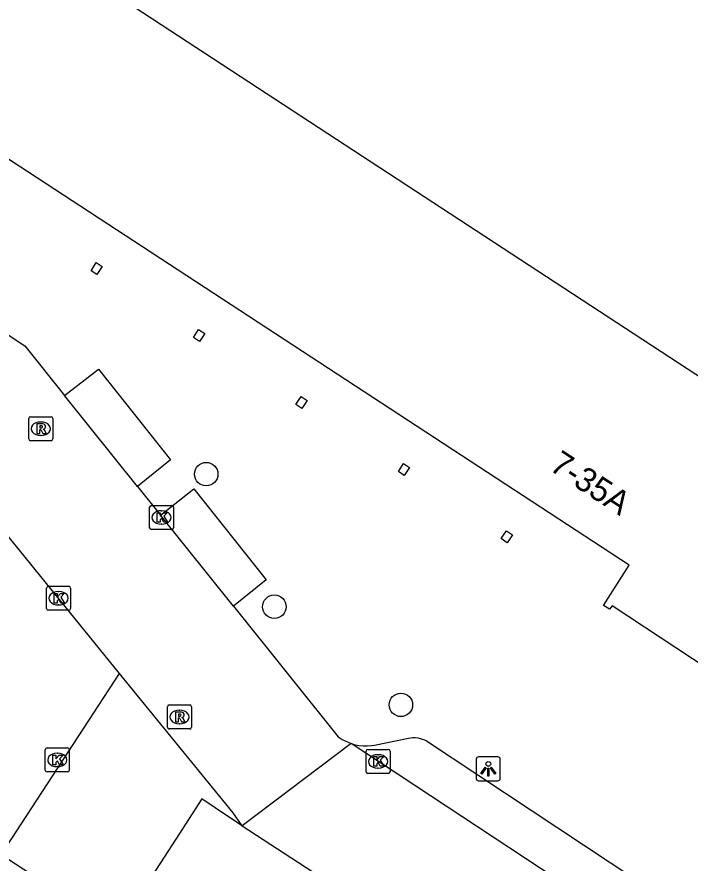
# Model space of a CAD drawing. Extents: x 159280 to 160375, y 384531 to 385872.
# Drawn here: x 159762.98 to 159791.01, y 385030.75 to 385066 of the extents above; entities that cross this region are included whole.
import ezdxf

# ---------------------------------------------------------------- set-up
doc = ezdxf.new("R2010")
doc.units = 0
for name, color, linetype in [('IMGEO_Boom', 7, 'Continuous'), ('IMGEO_Kolk', 7, 'Continuous'), ('IMGEO_Lichtpunt', 7, 'Continuous'), ('IMGEO_Pand', 7, 'Continuous'), ('IMGEO_Pand_nummerreeks', 7, 'Continuous'), ('IMGEO_Rijbaan_lokaal_open', 7, 'Continuous'), ('IMGEO_Rioolput', 7, 'Continuous'), ('IMGEO_Voetpad_open', 7, 'Continuous')]:
    doc.layers.add(name, color=color, linetype=linetype)

msp = doc.modelspace()

# ---------------------------------------------------------------- linework, layer by layer
at = {"layer": 'IMGEO_Boom'}
for centre in [(159770.864, 385046.949), (159773.702, 385041.427), (159778.971, 385037.338)]:
    msp.add_circle(centre, 0.489, dxfattribs=at)
at = {"layer": 'IMGEO_Kolk'}
for p, q in [((159768.506, 385044.718), (159768.506, 385045.57)), ((159768.581, 385045.644), (159769.433, 385045.644)), ((159769.507, 385045.57), (159769.507, 385044.718)), ((159768.994, 385045.424), (159769.019, 385045.424)), ((159769.017, 385044.864), (159768.992, 385044.864)), ((159769.433, 385044.644), (159768.581, 385044.644)), ((159764.218, 385041.352), (159764.218, 385042.204)), ((159764.293, 385042.278), (159765.145, 385042.278)), ((159764.706, 385042.058), (159764.731, 385042.058)), ((159765.219, 385042.204), (159765.219, 385041.352)), ((159765.145, 385041.278), (159764.293, 385041.278)), ((159764.729, 385041.498), (159764.704, 385041.498)), ((159764.164, 385034.618), (159764.164, 385035.47)), ((159764.239, 385035.544), (159765.091, 385035.544)), ((159764.652, 385035.324), (159764.677, 385035.324)), ((159765.165, 385035.47), (159765.165, 385034.618)), ((159777.518, 385034.554), (159777.518, 385035.406)), ((159777.593, 385035.48), (159778.445, 385035.48)), ((159778.006, 385035.26), (159778.031, 385035.26)), ((159778.519, 385035.406), (159778.519, 385034.554)), ((159765.091, 385034.544), (159764.239, 385034.544)), ((159764.675, 385034.764), (159764.65, 385034.764)), ((159778.029, 385034.7), (159778.004, 385034.7)), ((159778.445, 385034.48), (159777.593, 385034.48))]:
    msp.add_line(p, q, dxfattribs=at)
for points in [[(159768.506, 385044.718), (159768.506, 385045.57)], [(159768.581, 385045.644), (159769.433, 385045.644)], [(159769.507, 385045.57), (159769.507, 385044.718)], [(159768.827, 385045.344), (159768.95, 385045.344), (159768.95, 385045.193), (159769.08, 385045.344), (159769.244, 385045.344), (159769.098, 385045.193), (159769.251, 385044.944), (159769.099, 385044.944), (159769.014, 385045.108), (159768.95, 385045.041), (159768.95, 385044.944), (159768.827, 385044.944), (159768.827, 385045.344)], [(159769.433, 385044.644), (159768.581, 385044.644)], [(159764.218, 385041.352), (159764.218, 385042.204)], [(159764.293, 385042.278), (159765.145, 385042.278)], [(159764.539, 385041.978), (159764.662, 385041.978), (159764.662, 385041.827), (159764.792, 385041.978), (159764.956, 385041.978), (159764.81, 385041.827), (159764.963, 385041.578), (159764.811, 385041.578), (159764.726, 385041.742), (159764.662, 385041.675), (159764.662, 385041.578), (159764.539, 385041.578), (159764.539, 385041.978)], [(159765.219, 385042.204), (159765.219, 385041.352)], [(159765.145, 385041.278), (159764.293, 385041.278)], [(159764.164, 385034.618), (159764.164, 385035.47)], [(159764.239, 385035.544), (159765.091, 385035.544)], [(159764.485, 385035.244), (159764.608, 385035.244), (159764.608, 385035.093), (159764.738, 385035.244), (159764.902, 385035.244), (159764.756, 385035.093), (159764.909, 385034.844), (159764.757, 385034.844), (159764.672, 385035.008), (159764.608, 385034.941), (159764.608, 385034.844), (159764.485, 385034.844), (159764.485, 385035.244)], [(159765.165, 385035.47), (159765.165, 385034.618)], [(159777.518, 385034.554), (159777.518, 385035.406)], [(159777.593, 385035.48), (159778.445, 385035.48)], [(159778.519, 385035.406), (159778.519, 385034.554)], [(159777.839, 385035.18), (159777.962, 385035.18), (159777.962, 385035.029), (159778.092, 385035.18), (159778.256, 385035.18), (159778.11, 385035.029), (159778.263, 385034.78), (159778.111, 385034.78), (159778.026, 385034.944), (159777.962, 385034.877), (159777.962, 385034.78), (159777.839, 385034.78), (159777.839, 385035.18)], [(159765.091, 385034.544), (159764.239, 385034.544)], [(159778.445, 385034.48), (159777.593, 385034.48)]]:
    msp.add_lwpolyline(points, dxfattribs=at)
for centre, start, end in [((159768.583, 385045.568), 91.552, 178.448), ((159768.583, 385045.568), 91.552, 178.448), ((159769.431, 385045.568), 1.552, 88.448), ((159769.431, 385045.568), 1.552, 88.448), ((159768.583, 385044.72), 181.552, 268.448), ((159768.583, 385044.72), 181.552, 268.448), ((159769.431, 385044.72), 271.552, 358.448), ((159769.431, 385044.72), 271.552, 358.448), ((159764.295, 385042.202), 91.552, 178.448), ((159764.295, 385042.202), 91.552, 178.448), ((159765.143, 385042.202), 1.552, 88.448), ((159765.143, 385042.202), 1.552, 88.448), ((159764.295, 385041.354), 181.552, 268.448), ((159764.295, 385041.354), 181.552, 268.448), ((159765.143, 385041.354), 271.552, 358.448), ((159765.143, 385041.354), 271.552, 358.448), ((159764.241, 385035.468), 91.552, 178.448), ((159764.241, 385035.468), 91.552, 178.448), ((159765.089, 385035.468), 1.552, 88.448), ((159765.089, 385035.468), 1.552, 88.448), ((159777.595, 385035.404), 91.552, 178.448), ((159777.595, 385035.404), 91.552, 178.448), ((159778.443, 385035.404), 1.552, 88.448), ((159778.443, 385035.404), 1.552, 88.448), ((159764.241, 385034.62), 181.552, 268.448), ((159764.241, 385034.62), 181.552, 268.448), ((159765.089, 385034.62), 271.552, 358.448), ((159765.089, 385034.62), 271.552, 358.448), ((159777.595, 385034.556), 181.552, 268.448), ((159777.595, 385034.556), 181.552, 268.448), ((159778.443, 385034.556), 271.552, 358.448), ((159778.443, 385034.556), 271.552, 358.448)]:
    msp.add_arc(centre, 0.0765, start, end, dxfattribs=at)
for centre, major_axis, ratio, start_param, end_param in [((159768.993, 385045.144), (-0.387, 0.002), 0.722429, 4.712389, 7.853982), ((159769.018, 385045.144), (-0.39, 0.002), 0.717154, 1.570796, 4.712389), ((159764.705, 385041.778), (-0.387, 0.002), 0.722429, 4.712389, 7.853982), ((159764.73, 385041.778), (-0.39, 0.002), 0.717154, 1.570796, 4.712389), ((159764.651, 385035.044), (-0.387, 0.002), 0.722429, 4.712389, 7.853982), ((159764.676, 385035.044), (-0.39, 0.002), 0.717154, 1.570796, 4.712389), ((159778.005, 385034.98), (-0.387, 0.002), 0.722429, 4.712389, 7.853982), ((159778.03, 385034.98), (-0.39, 0.002), 0.717154, 1.570796, 4.712389)]:
    msp.add_ellipse(centre, major_axis=major_axis, ratio=ratio, start_param=start_param, end_param=end_param, dxfattribs=at)
at = {"layer": 'IMGEO_Lichtpunt'}
for p, q in [((159782.11, 385035.078), (159782.11, 385034.271)), ((159782.11, 385035.078), (159782.11, 385034.271)), ((159783.012, 385035.173), (159782.204, 385035.173)), ((159783.012, 385035.173), (159782.204, 385035.173)), ((159783.106, 385034.271), (159783.106, 385035.078)), ((159783.106, 385034.271), (159783.106, 385035.078)), ((159782.204, 385034.177), (159783.012, 385034.177)), ((159782.204, 385034.177), (159783.012, 385034.177))]:
    msp.add_line(p, q, dxfattribs=at)
for points in [[(159782.484, 385034.742), (159782.523, 385034.714), (159782.335, 385034.452), (159782.297, 385034.479), (159782.484, 385034.742)], [(159782.586, 385034.694), (159782.633, 385034.694), (159782.633, 385034.372), (159782.586, 385034.372), (159782.586, 385034.694)], [(159782.696, 385034.714), (159782.734, 385034.741), (159782.921, 385034.479), (159782.882, 385034.451), (159782.696, 385034.714)]]:
    msp.add_lwpolyline(points, dxfattribs=at)
msp.add_circle((159782.609, 385034.876), 0.0994, dxfattribs=at)
for centre, start, end in [((159782.204, 385035.078), 90, 180), ((159782.204, 385035.078), 90, 180), ((159783.012, 385035.078), 0, 90), ((159783.012, 385035.078), 0, 90), ((159782.204, 385034.271), 180, 270), ((159782.204, 385034.271), 180, 270), ((159783.012, 385034.271), 270, 0), ((159783.012, 385034.271), 270, 360)]:
    msp.add_arc(centre, 0.0946, start, end, dxfattribs=at)
at = {"layer": 'IMGEO_Pand'}
for points in [[(159758.939, 385075.975), (159757.257, 385073.372), (159759.826, 385071.675), (159812.424, 385037.26), (159815.331, 385041.68), (159815.513, 385041.56)], [(159791.768, 385038.831), (159787.771, 385041.458), (159787.659, 385041.318), (159787.407, 385041.476), (159788.477, 385043.151), (159750.544, 385067.986), (159749.427, 385066.306), (159744.541, 385069.513)], [(159766.281, 385055.765), (159766.535, 385055.599), (159766.315, 385055.266), (159766.072, 385055.423), (159766.281, 385055.765)], [(159770.542, 385052.975), (159770.801, 385052.81), (159770.582, 385052.476), (159770.331, 385052.637), (159770.542, 385052.975)], [(159774.812, 385050.183), (159775.065, 385050.017), (159774.846, 385049.683), (159774.601, 385049.845), (159774.812, 385050.183)], [(159779.078, 385047.396), (159779.332, 385047.231), (159779.113, 385046.896), (159778.866, 385047.056), (159779.078, 385047.396)], [(159783.366, 385044.593), (159783.62, 385044.428), (159783.401, 385044.093), (159783.14, 385044.267), (159783.366, 385044.593)]]:
    msp.add_lwpolyline(points, dxfattribs=at)
at = {"layer": 'IMGEO_Rijbaan_lokaal_open'}
for points in [[(159762.407, 385052.895), (159763.312, 385052.296), (159764.967, 385050.229)], [(159768.003, 385046.438), (159764.967, 385050.229)], [(159768.003, 385046.438), (159768.959, 385045.245)], [(159771.997, 385041.451), (159768.959, 385045.245)], [(159767.259, 385038.65), (159762.49, 385044.521)], [(159771.997, 385041.451), (159776.359, 385036.004), (159776.519, 385035.899), (159776.906, 385035.721)], [(159762.324, 385031.093), (159767.259, 385038.65)], [(159772.362, 385032.302), (159771.983, 385032.834), (159767.259, 385038.65)], [(159776.906, 385035.721), (159772.362, 385032.302)], [(159803.235, 385018.337), (159776.906, 385035.721)], [(159772.362, 385032.302), (159780.636, 385026.908)]]:
    msp.add_lwpolyline(points, dxfattribs=at)
at = {"layer": 'IMGEO_Rioolput'}
for p, q in [((159763.552, 385049.342), (159764.404, 385049.342)), ((159763.477, 385048.416), (159763.477, 385049.268)), ((159763.965, 385049.122), (159763.99, 385049.122)), ((159764.478, 385049.268), (159764.478, 385048.416)), ((159764.404, 385048.342), (159763.552, 385048.342)), ((159763.988, 385048.562), (159763.963, 385048.562)), ((159769.249, 385036.406), (159769.249, 385037.258)), ((159769.324, 385037.332), (159770.176, 385037.332)), ((159769.737, 385037.112), (159769.762, 385037.112)), ((159770.25, 385037.258), (159770.25, 385036.406)), ((159770.176, 385036.332), (159769.324, 385036.332)), ((159769.76, 385036.552), (159769.735, 385036.552))]:
    msp.add_line(p, q, dxfattribs=at)
for points in [[(159763.552, 385049.342), (159764.404, 385049.342)], [(159763.477, 385048.416), (159763.477, 385049.268)], [(159764.066, 385049.04), (159763.814, 385049.042), (159763.814, 385048.642)], [(159764.478, 385049.268), (159764.478, 385048.416)], [(159763.814, 385048.642), (159763.938, 385048.642), (159763.938, 385048.804), (159763.949, 385048.804)], [(159763.992, 385048.961), (159763.938, 385048.961), (159763.938, 385048.88)], [(159763.938, 385048.88), (159763.99, 385048.88)], [(159763.996, 385048.775), (159764.067, 385048.642), (159764.207, 385048.642), (159764.142, 385048.768)], [(159764.404, 385048.342), (159763.552, 385048.342)], [(159769.249, 385036.406), (159769.249, 385037.258)], [(159769.324, 385037.332), (159770.176, 385037.332)], [(159769.838, 385037.03), (159769.586, 385037.032), (159769.586, 385036.632)], [(159770.25, 385037.258), (159770.25, 385036.406)], [(159769.586, 385036.632), (159769.71, 385036.632), (159769.71, 385036.794), (159769.721, 385036.794)], [(159769.764, 385036.951), (159769.71, 385036.951), (159769.71, 385036.87)], [(159769.71, 385036.87), (159769.762, 385036.87)], [(159769.768, 385036.765), (159769.839, 385036.632), (159769.979, 385036.632), (159769.914, 385036.758)], [(159770.176, 385036.332), (159769.324, 385036.332)]]:
    msp.add_lwpolyline(points, dxfattribs=at)
for centre, radius, start, end in [((159763.554, 385049.266), 0.0765, 91.552, 178.448), ((159763.554, 385049.266), 0.0765, 91.552, 178.448), ((159764.402, 385049.266), 0.0765, 1.552, 88.448), ((159764.402, 385049.266), 0.0765, 1.552, 88.448), ((159764.065, 385048.93), 0.109, 350.3612, 89.416), ((159763.948, 385048.751), 0.0533, 26.0293, 88.6989), ((159763.974, 385049.069), 0.19, 274.7715, 282.9687), ((159763.998, 385048.865), 0.0964, 77.0061, 93.1865), ((159764.012, 385048.922), 0.0378, 276.6634, 79.6772), ((159764.063, 385048.93), 0.112, 277.5842, 350.9817), ((159764.047, 385048.715), 0.108, 29.5134, 73.7905), ((159763.554, 385048.418), 0.0765, 181.552, 268.448), ((159763.554, 385048.418), 0.0765, 181.552, 268.448), ((159764.402, 385048.418), 0.0765, 271.552, 358.448), ((159764.402, 385048.418), 0.0765, 271.552, 358.448), ((159769.326, 385037.256), 0.0765, 91.552, 178.448), ((159769.326, 385037.256), 0.0765, 91.552, 178.448), ((159769.837, 385036.92), 0.109, 350.3612, 89.416), ((159770.174, 385037.256), 0.0765, 1.552, 88.448), ((159770.174, 385037.256), 0.0765, 1.552, 88.448), ((159769.72, 385036.741), 0.0533, 26.0293, 88.6989), ((159769.746, 385037.059), 0.19, 274.7715, 282.9687), ((159769.77, 385036.855), 0.0964, 77.0061, 93.1865), ((159769.784, 385036.912), 0.0378, 276.6634, 79.6772), ((159769.835, 385036.92), 0.112, 277.5842, 350.9817), ((159769.819, 385036.705), 0.108, 29.5134, 73.7905), ((159769.326, 385036.408), 0.0765, 181.552, 268.448), ((159769.326, 385036.408), 0.0765, 181.552, 268.448), ((159770.174, 385036.408), 0.0765, 271.552, 358.448), ((159770.174, 385036.408), 0.0765, 271.552, 358.448)]:
    msp.add_arc(centre, radius, start, end, dxfattribs=at)
for centre, major_axis, ratio, start_param, end_param in [((159763.964, 385048.842), (-0.387, 0.002), 0.722429, 4.712389, 7.853982), ((159763.989, 385048.842), (-0.39, 0.002), 0.717154, 1.570796, 4.712389), ((159769.736, 385036.832), (-0.387, 0.002), 0.722429, 4.712389, 7.853982), ((159769.761, 385036.832), (-0.39, 0.002), 0.717154, 1.570796, 4.712389)]:
    msp.add_ellipse(centre, major_axis=major_axis, ratio=ratio, start_param=start_param, end_param=end_param, dxfattribs=at)
at = {"layer": 'IMGEO_Voetpad_open'}
for points in [[(159764.967, 385050.229), (159766.381, 385051.32), (159769.384, 385047.543), (159768.003, 385046.438)], [(159768.959, 385045.245), (159770.347, 385046.342), (159773.357, 385042.547), (159771.997, 385041.451)], [(159776.906, 385035.721), (159777.069, 385035.675), (159777.235, 385035.644), (159777.403, 385035.628), (159777.572, 385035.627), (159777.74, 385035.641), (159777.869, 385035.662), (159779.285, 385035.956), (159779.373, 385035.969), (159779.472, 385035.976), (159779.571, 385035.974), (159779.669, 385035.963), (159779.766, 385035.943), (159779.86, 385035.914), (159779.952, 385035.878), (159780.04, 385035.833), (159801.828, 385021.396)], [(159772.362, 385032.302), (159771.795, 385032.678), (159770.679, 385033.418), (159769.593, 385031.74), (159767.138, 385027.949), (159762.324, 385031.093)]]:
    msp.add_lwpolyline(points, dxfattribs=at)

# ---------------------------------------------------------------- texts
at = {"layer": 'IMGEO_Pand_nummerreeks'}
msp.add_text('7-35A', height=1, rotation=326.7856, dxfattribs=at).set_placement((159785.104, 385047.152))

doc.saveas('drawing.dxf')
